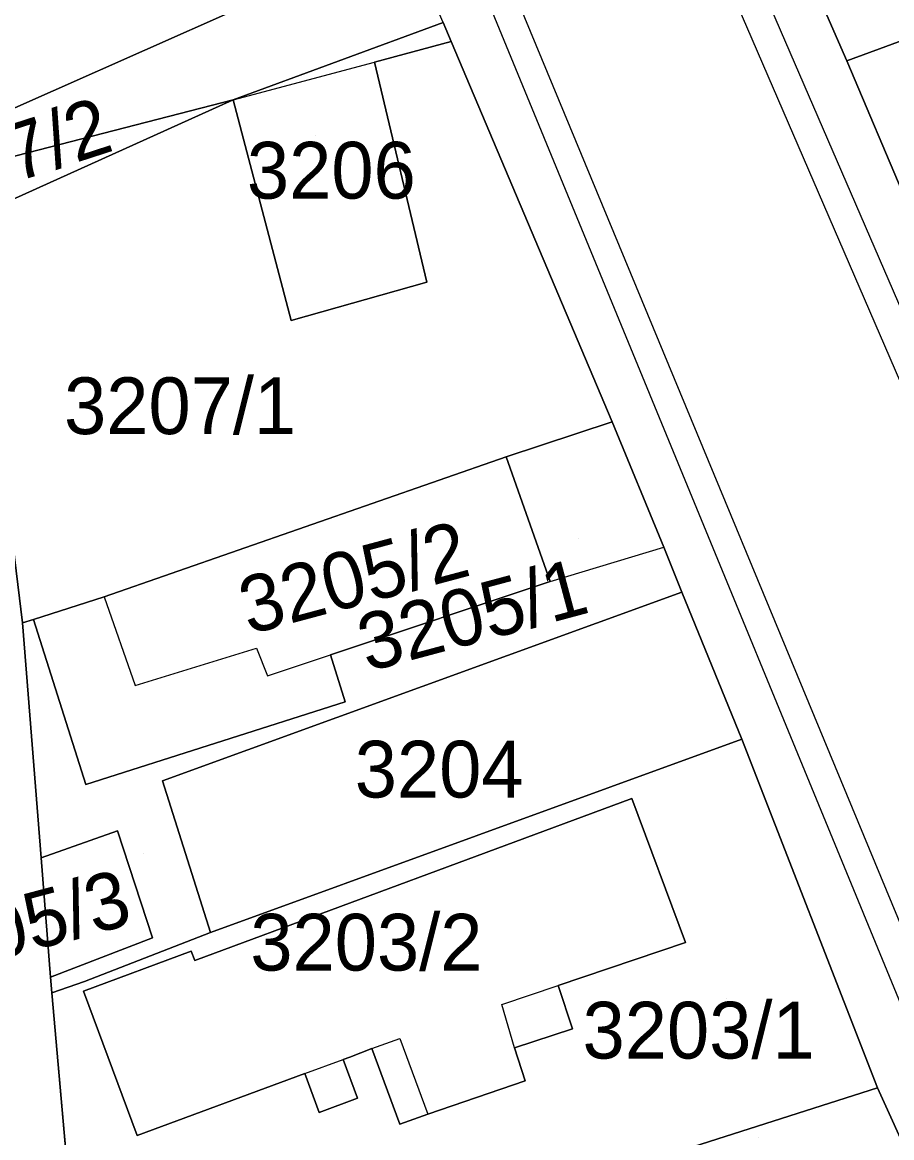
# Model space of a CAD drawing. Extents: x -262657 to -261595, y -1238015 to -1237156.
# Drawn here: x -261921.51 to -261890.88, y -1237853.34 to -1237814.02 of the extents above; entities that cross this region are included whole.
import ezdxf

# ---------------------------------------------------------------- set-up
doc = ezdxf.new("R2010")
doc.units = 0
for name, color, linetype in [('body_kn', 7, 'Continuous'), ('kladpar_druhypozemkov', 7, 'Continuous'), ('kladpar_hranice', 7, 'Continuous'), ('kladpar_parcelnecisla', 7, 'Continuous'), ('kladpar_plochy', 7, 'Continuous'), ('zappar_hrandruhpozemk', 7, 'Continuous')]:
    doc.layers.add(name, color=color, linetype=linetype)

msp = doc.modelspace()

# ---------------------------------------------------------------- linework, layer by layer
at = {"layer": 'body_kn'}
for p, q in [((-261906.69, -1237814.03), (-261906.69, -1237814.03)), ((-261906.69, -1237814.03), (-261906.69, -1237814.03)), ((-261906.4, -1237814.7), (-261906.4, -1237814.7)), ((-261906.4, -1237814.7), (-261906.4, -1237814.7)), ((-261909.1, -1237815.43), (-261909.1, -1237815.43)), ((-261909.1, -1237815.43), (-261909.1, -1237815.43)), ((-261892.46, -1237815.38), (-261892.46, -1237815.38)), ((-261892.46, -1237815.38), (-261892.46, -1237815.38)), ((-261914.09, -1237816.76), (-261914.09, -1237816.76)), ((-261914.09, -1237816.76), (-261914.09, -1237816.76)), ((-261907.26, -1237823.18), (-261907.26, -1237823.18)), ((-261912.04, -1237824.53), (-261912.04, -1237824.53)), ((-261900.73, -1237828.11), (-261900.73, -1237828.11)), ((-261904.47, -1237829.34), (-261904.47, -1237829.34)), ((-261904.47, -1237829.34), (-261904.47, -1237829.34)), ((-261898.91, -1237832.53), (-261898.91, -1237832.53)), ((-261902.91, -1237833.74), (-261902.91, -1237833.74)), ((-261902.91, -1237833.74), (-261902.91, -1237833.74)), ((-261918.63, -1237834.28), (-261918.63, -1237834.28)), ((-261918.63, -1237834.28), (-261918.63, -1237834.28)), ((-261898.28, -1237834.11), (-261898.28, -1237834.11)), ((-261898.28, -1237834.11), (-261898.28, -1237834.11)), ((-261921.12, -1237835.07), (-261921.12, -1237835.07)), ((-261921.12, -1237835.07), (-261921.12, -1237835.07)), ((-261921.51, -1237835.19), (-261921.51, -1237835.19)), ((-261913.26, -1237836.08), (-261913.26, -1237836.08)), ((-261910.65, -1237836.32), (-261910.65, -1237836.32)), ((-261912.88, -1237837.06), (-261912.88, -1237837.06)), ((-261917.54, -1237837.4), (-261917.54, -1237837.4)), ((-261910.14, -1237837.98), (-261910.14, -1237837.98)), ((-261896.16, -1237839.29), (-261896.16, -1237839.29)), ((-261919.28, -1237840.89), (-261919.28, -1237840.89)), ((-261916.58, -1237840.76), (-261916.58, -1237840.76)), ((-261900.04, -1237841.39), (-261900.04, -1237841.39)), ((-261918.16, -1237842.52), (-261918.16, -1237842.52)), ((-261920.85, -1237843.48), (-261920.85, -1237843.48)), ((-261920.85, -1237843.48), (-261920.85, -1237843.48)), ((-261914.88, -1237846.11), (-261914.88, -1237846.11)), ((-261916.93, -1237846.3), (-261916.93, -1237846.3)), ((-261898.14, -1237846.46), (-261898.14, -1237846.46)), ((-261915.56, -1237846.76), (-261915.56, -1237846.76)), ((-261915.44, -1237847.09), (-261915.44, -1237847.09)), ((-261920.52, -1237847.68), (-261920.52, -1237847.68)), ((-261919.32, -1237847.83), (-261919.32, -1237847.83)), ((-261902.63, -1237847.97), (-261902.63, -1237847.97)), ((-261920.48, -1237848.23), (-261920.48, -1237848.23)), ((-261920.48, -1237848.23), (-261920.48, -1237848.23)), ((-261919.36, -1237848.17), (-261919.36, -1237848.17)), ((-261919.36, -1237848.17), (-261919.36, -1237848.17)), ((-261904.62, -1237848.64), (-261904.62, -1237848.64)), ((-261902.13, -1237849.5), (-261902.13, -1237849.5)), ((-261908.21, -1237849.84), (-261908.21, -1237849.84)), ((-261909.2, -1237850.2), (-261909.2, -1237850.2)), ((-261909.2, -1237850.2), (-261909.2, -1237850.2)), ((-261904.17, -1237850.17), (-261904.17, -1237850.17)), ((-261904.17, -1237850.17), (-261904.17, -1237850.17)), ((-261910.21, -1237850.58), (-261910.21, -1237850.58)), ((-261909.97, -1237850.5), (-261909.97, -1237850.5)), ((-261911.56, -1237851.08), (-261911.56, -1237851.08)), ((-261911.56, -1237851.08), (-261911.56, -1237851.08)), ((-261903.79, -1237851.33), (-261903.79, -1237851.33)), ((-261891.38, -1237851.58), (-261891.38, -1237851.58)), ((-261891.38, -1237851.58), (-261891.38, -1237851.58)), ((-261909.7, -1237851.95), (-261909.7, -1237851.95)), ((-261911.05, -1237852.45), (-261911.05, -1237852.45)), ((-261907.22, -1237852.51), (-261907.22, -1237852.51)), ((-261908.21, -1237852.86), (-261908.21, -1237852.86)), ((-261917.47, -1237853.26), (-261917.47, -1237853.26)), ((-261895.57, -1237853.34), (-261895.57, -1237853.34))]:
    msp.add_line(p, q, dxfattribs=at)
at = {"layer": 'kladpar_druhypozemkov'}
for p, q in [((-261918.2, -1237818.16), (-261918.2, -1237818.16)), ((-261911.17, -1237818.03), (-261911.17, -1237818.03)), ((-261915.41, -1237826.93), (-261915.41, -1237826.93)), ((-261901.91, -1237832.22), (-261901.91, -1237832.22)), ((-261910.79, -1237832.7), (-261910.79, -1237832.7)), ((-261906.47, -1237839.89), (-261906.47, -1237839.89)), ((-261917.23, -1237843.33), (-261917.23, -1237843.33)), ((-261919.17, -1237844.63), (-261919.17, -1237844.63)), ((-261907.88, -1237845.63), (-261907.88, -1237845.63)), ((-261896.71, -1237848.43), (-261896.71, -1237848.43))]:
    msp.add_line(p, q, dxfattribs=at)
at = {"layer": 'kladpar_hranice'}
for points in [[(-261914.09, -1237816.76), (-261923.62, -1237819.21), (-261923.89, -1237818.34), (-261924, -1237817.96), (-261923.67, -1237817.87), (-261913.97, -1237813.57), (-261908.88, -1237811.31), (-261912.8, -1237801.81), (-261914.12, -1237798.61), (-261922.63, -1237778.24), (-261926.09, -1237769.65), (-261929.76, -1237759.16), (-261940.37, -1237728.85), (-261943.02, -1237721.29), (-261943.45, -1237719.94), (-261944.94, -1237715.14), (-261945.5, -1237713.33), (-261947.79, -1237697.89), (-261949.17, -1237690.86), (-261949.54, -1237688.95), (-261951.01, -1237681.71), (-261952.29, -1237673.66)], [(-261892.46, -1237815.38), (-261897.39, -1237804.1), (-261895.22, -1237803.36), (-261886.03, -1237800.22), (-261882.66, -1237799.08), (-261875.2, -1237796.53), (-261874.46, -1237799.37), (-261878.83, -1237801.48), (-261876.32, -1237809.44), (-261892.46, -1237815.38)], [(-261924.11, -1237817.62), (-261925.24, -1237804.88), (-261912.8, -1237801.81), (-261908.88, -1237811.31), (-261913.97, -1237813.57), (-261923.67, -1237817.87), (-261924, -1237817.96), (-261924.11, -1237817.62)], [(-261897.39, -1237804.1), (-261892.46, -1237815.38), (-261890.38, -1237820.3), (-261888.53, -1237824.53), (-261885.29, -1237831.79), (-261884.38, -1237833.72), (-261884, -1237834.66), (-261881.91, -1237839.28), (-261881.21, -1237840.86), (-261879.01, -1237845.76), (-261874.52, -1237855.64), (-261873.52, -1237857.83), (-261867.67, -1237871.68), (-261864.24, -1237879.6), (-261863.85, -1237880.67), (-261862.42, -1237883.92), (-261860.37, -1237888.77), (-261858.89, -1237892.19), (-261858.36, -1237893.51), (-261854.78, -1237901.75)], [(-261890.38, -1237820.3), (-261892.46, -1237815.38), (-261876.32, -1237809.44), (-261874, -1237808.64), (-261873.82, -1237809.05), (-261875.21, -1237809.56), (-261873.73, -1237813.58), (-261875.04, -1237813.91), (-261878.43, -1237816.1), (-261890.38, -1237820.3)], [(-261909.1, -1237815.43), (-261907.26, -1237823.18), (-261912.04, -1237824.53), (-261914.09, -1237816.76), (-261906.69, -1237814.03), (-261906.4, -1237814.7), (-261909.1, -1237815.43)], [(-261867.89, -1237908.17), (-261869.84, -1237903.85), (-261871.28, -1237900.38), (-261871.81, -1237899.1), (-261875.73, -1237889.62), (-261876.97, -1237886.62), (-261878.89, -1237882.22), (-261879.83, -1237879.78), (-261882.36, -1237872.9), (-261884.52, -1237867.46), (-261886.78, -1237861.7), (-261887.83, -1237859.39), (-261891.38, -1237851.58), (-261896.16, -1237839.29), (-261898.28, -1237834.11), (-261898.91, -1237832.53), (-261900.73, -1237828.11), (-261906.4, -1237814.7), (-261906.69, -1237814.03), (-261914.09, -1237816.76)], [(-261906.4, -1237814.7), (-261900.73, -1237828.11), (-261904.47, -1237829.34), (-261918.63, -1237834.28), (-261921.12, -1237835.07), (-261921.51, -1237835.19), (-261922.58, -1237826.51), (-261922.91, -1237823.77), (-261923.32, -1237821.16), (-261923.35, -1237820.94), (-261914.09, -1237816.76), (-261912.04, -1237824.53), (-261907.26, -1237823.18), (-261909.1, -1237815.43), (-261906.4, -1237814.7)], [(-261923.35, -1237820.94), (-261923.36, -1237820.86), (-261923.62, -1237819.21), (-261914.09, -1237816.76), (-261923.35, -1237820.94)], [(-261922.58, -1237826.51), (-261921.51, -1237835.19), (-261920.85, -1237843.48), (-261920.52, -1237847.68), (-261920.48, -1237848.23), (-261919.39, -1237860.46), (-261943.52, -1237862.78), (-261943.56, -1237862.36), (-261945.19, -1237844.04)], [(-261904.47, -1237829.34), (-261900.73, -1237828.11), (-261898.91, -1237832.53), (-261898.28, -1237834.11), (-261916.58, -1237840.76), (-261914.88, -1237846.11), (-261919.32, -1237847.83), (-261920.48, -1237848.23), (-261920.52, -1237847.68), (-261916.93, -1237846.3), (-261918.16, -1237842.52), (-261920.85, -1237843.48), (-261921.51, -1237835.19), (-261921.12, -1237835.07), (-261919.28, -1237840.89), (-261910.14, -1237837.98), (-261910.65, -1237836.32), (-261902.91, -1237833.74), (-261904.47, -1237829.34)], [(-261921.12, -1237835.07), (-261918.63, -1237834.28), (-261904.47, -1237829.34), (-261902.91, -1237833.74), (-261910.65, -1237836.32), (-261910.14, -1237837.98), (-261919.28, -1237840.89), (-261921.12, -1237835.07)], [(-261898.28, -1237834.11), (-261896.16, -1237839.29), (-261914.88, -1237846.11), (-261916.58, -1237840.76), (-261898.28, -1237834.11)], [(-261920.48, -1237848.23), (-261919.32, -1237847.83), (-261914.88, -1237846.11), (-261896.16, -1237839.29)], [(-261896.16, -1237839.29), (-261891.38, -1237851.58), (-261909.18, -1237857.27)], [(-261900.04, -1237841.39), (-261915.44, -1237847.09), (-261915.56, -1237846.76), (-261919.36, -1237848.17), (-261917.47, -1237853.26), (-261911.56, -1237851.08), (-261911.05, -1237852.45), (-261909.7, -1237851.95), (-261910.21, -1237850.58), (-261909.97, -1237850.5), (-261909.2, -1237850.2), (-261908.21, -1237852.86), (-261907.22, -1237852.51), (-261903.79, -1237851.33), (-261904.17, -1237850.17), (-261902.13, -1237849.5), (-261902.63, -1237847.97), (-261898.14, -1237846.46), (-261900.04, -1237841.39)], [(-261919.36, -1237848.17), (-261915.56, -1237846.76), (-261915.44, -1237847.09), (-261900.04, -1237841.39), (-261898.14, -1237846.46), (-261902.63, -1237847.97), (-261902.13, -1237849.5), (-261904.17, -1237850.17), (-261903.79, -1237851.33), (-261907.22, -1237852.51), (-261908.21, -1237852.86), (-261909.2, -1237850.2), (-261909.97, -1237850.5), (-261910.21, -1237850.58), (-261909.7, -1237851.95), (-261911.05, -1237852.45), (-261911.56, -1237851.08), (-261917.47, -1237853.26), (-261919.36, -1237848.17)], [(-261920.85, -1237843.48), (-261918.16, -1237842.52), (-261916.93, -1237846.3), (-261920.52, -1237847.68), (-261920.85, -1237843.48)], [(-261909.18, -1237857.27), (-261919.39, -1237860.46), (-261920.48, -1237848.23)], [(-261891.38, -1237851.58), (-261887.83, -1237859.39), (-261886.78, -1237861.7), (-261892.76, -1237864.26), (-261904.35, -1237869.07), (-261909.18, -1237857.27), (-261891.38, -1237851.58)]]:
    msp.add_lwpolyline(points, dxfattribs=at)
at = {"layer": 'kladpar_plochy'}
for p, q in [((-261914.88, -1237846.11), (-261896.16, -1237839.29)), ((-261896.16, -1237839.29), (-261891.38, -1237851.58)), ((-261900.04, -1237841.39), (-261915.44, -1237847.09)), ((-261898.14, -1237846.46), (-261900.04, -1237841.39)), ((-261919.32, -1237847.83), (-261914.88, -1237846.11)), ((-261902.63, -1237847.97), (-261898.14, -1237846.46)), ((-261915.56, -1237846.76), (-261919.36, -1237848.17)), ((-261915.44, -1237847.09), (-261915.56, -1237846.76)), ((-261920.48, -1237848.23), (-261919.32, -1237847.83)), ((-261902.13, -1237849.5), (-261902.63, -1237847.97)), ((-261919.39, -1237860.46), (-261920.48, -1237848.23)), ((-261919.36, -1237848.17), (-261917.47, -1237853.26)), ((-261904.17, -1237850.17), (-261902.13, -1237849.5)), ((-261909.97, -1237850.5), (-261909.2, -1237850.2)), ((-261909.2, -1237850.2), (-261908.21, -1237852.86)), ((-261903.79, -1237851.33), (-261904.17, -1237850.17)), ((-261910.21, -1237850.58), (-261909.97, -1237850.5)), ((-261909.7, -1237851.95), (-261910.21, -1237850.58)), ((-261917.47, -1237853.26), (-261911.56, -1237851.08)), ((-261911.56, -1237851.08), (-261911.05, -1237852.45)), ((-261891.38, -1237851.58), (-261909.18, -1237857.27)), ((-261907.22, -1237852.51), (-261903.79, -1237851.33)), ((-261911.05, -1237852.45), (-261909.7, -1237851.95)), ((-261908.21, -1237852.86), (-261907.22, -1237852.51))]:
    msp.add_line(p, q, dxfattribs=at)
for points in [[(-261892.46, -1237815.38), (-261897.39, -1237804.1), (-261895.22, -1237803.36), (-261886.03, -1237800.22), (-261882.66, -1237799.08), (-261875.2, -1237796.53), (-261874.46, -1237799.37), (-261878.83, -1237801.48), (-261876.32, -1237809.44)], [(-261924.11, -1237817.62), (-261925.24, -1237804.88), (-261912.8, -1237801.81), (-261908.88, -1237811.31), (-261913.97, -1237813.57), (-261923.67, -1237817.87), (-261924, -1237817.96)], [(-261890.38, -1237820.3), (-261892.46, -1237815.38), (-261876.32, -1237809.44), (-261874, -1237808.64), (-261873.82, -1237809.05), (-261875.21, -1237809.56), (-261873.73, -1237813.58), (-261875.04, -1237813.91), (-261878.43, -1237816.1)], [(-261909.1, -1237815.43), (-261907.26, -1237823.18), (-261912.04, -1237824.53), (-261914.09, -1237816.76), (-261906.69, -1237814.03), (-261906.4, -1237814.7)], [(-261906.4, -1237814.7), (-261900.73, -1237828.11), (-261904.47, -1237829.34), (-261918.63, -1237834.28), (-261921.12, -1237835.07), (-261921.51, -1237835.19), (-261922.58, -1237826.51), (-261922.91, -1237823.77), (-261923.32, -1237821.16), (-261923.35, -1237820.94), (-261914.09, -1237816.76), (-261912.04, -1237824.53), (-261907.26, -1237823.18), (-261909.1, -1237815.43)], [(-261923.35, -1237820.94), (-261923.36, -1237820.86), (-261923.62, -1237819.21), (-261914.09, -1237816.76)], [(-261945.19, -1237844.04), (-261926.38, -1237842.67), (-261926.52, -1237835.51), (-261930.89, -1237835.7), (-261931.15, -1237832.29), (-261942.76, -1237833.21), (-261946.3, -1237833.58), (-261946.74, -1237828.94), (-261922.58, -1237826.51), (-261921.51, -1237835.19), (-261920.85, -1237843.48), (-261920.52, -1237847.68), (-261920.48, -1237848.23), (-261919.39, -1237860.46), (-261943.52, -1237862.78), (-261943.56, -1237862.36)], [(-261904.47, -1237829.34), (-261900.73, -1237828.11), (-261898.91, -1237832.53), (-261898.28, -1237834.11), (-261916.58, -1237840.76), (-261914.88, -1237846.11), (-261919.32, -1237847.83), (-261920.48, -1237848.23), (-261920.52, -1237847.68), (-261916.93, -1237846.3), (-261918.16, -1237842.52), (-261920.85, -1237843.48), (-261921.51, -1237835.19), (-261921.12, -1237835.07), (-261919.28, -1237840.89), (-261910.14, -1237837.98), (-261910.65, -1237836.32), (-261902.91, -1237833.74)], [(-261921.12, -1237835.07), (-261918.63, -1237834.28), (-261904.47, -1237829.34), (-261902.91, -1237833.74), (-261910.65, -1237836.32), (-261910.14, -1237837.98), (-261919.28, -1237840.89)], [(-261898.28, -1237834.11), (-261896.16, -1237839.29), (-261914.88, -1237846.11), (-261916.58, -1237840.76)], [(-261919.36, -1237848.17), (-261915.56, -1237846.76), (-261915.44, -1237847.09), (-261900.04, -1237841.39), (-261898.14, -1237846.46), (-261902.63, -1237847.97), (-261902.13, -1237849.5), (-261904.17, -1237850.17), (-261903.79, -1237851.33), (-261907.22, -1237852.51), (-261908.21, -1237852.86), (-261909.2, -1237850.2), (-261909.97, -1237850.5), (-261910.21, -1237850.58), (-261909.7, -1237851.95), (-261911.05, -1237852.45), (-261911.56, -1237851.08), (-261917.47, -1237853.26)], [(-261920.85, -1237843.48), (-261918.16, -1237842.52), (-261916.93, -1237846.3), (-261920.52, -1237847.68)], [(-261891.38, -1237851.58), (-261887.83, -1237859.39), (-261886.78, -1237861.7), (-261892.76, -1237864.26), (-261904.35, -1237869.07), (-261909.18, -1237857.27)]]:
    msp.add_lwpolyline(points, close=True, dxfattribs=at)
for points in [[(-261897.39, -1237804.1), (-261892.46, -1237815.38), (-261890.38, -1237820.3), (-261888.53, -1237824.53), (-261885.29, -1237831.79), (-261884.38, -1237833.72), (-261884, -1237834.66), (-261881.91, -1237839.28), (-261881.21, -1237840.86), (-261879.01, -1237845.76), (-261874.52, -1237855.64), (-261873.52, -1237857.83), (-261867.67, -1237871.68), (-261864.24, -1237879.6), (-261863.85, -1237880.67), (-261862.42, -1237883.92), (-261860.37, -1237888.77), (-261858.89, -1237892.19), (-261858.36, -1237893.51), (-261854.78, -1237901.75)], [(-261871.81, -1237899.1), (-261875.73, -1237889.62), (-261876.97, -1237886.62), (-261878.89, -1237882.22), (-261879.83, -1237879.78), (-261882.36, -1237872.9), (-261884.52, -1237867.46), (-261886.78, -1237861.7), (-261887.83, -1237859.39), (-261891.38, -1237851.58), (-261896.16, -1237839.29), (-261898.28, -1237834.11), (-261898.91, -1237832.53), (-261900.73, -1237828.11), (-261906.4, -1237814.7), (-261906.69, -1237814.03), (-261914.09, -1237816.76), (-261923.62, -1237819.21), (-261923.89, -1237818.34), (-261924, -1237817.96), (-261923.67, -1237817.87), (-261913.97, -1237813.57)]]:
    msp.add_lwpolyline(points, dxfattribs=at)
at = {"layer": 'zappar_hrandruhpozemk'}
for p, q in [((-261924.51, -1237745.6), (-261870.74, -1237869.97)), ((-261906.69, -1237814.03), (-261912.03, -1237801.62)), ((-261914.09, -1237816.76), (-261909.1, -1237815.43)), ((-261902.91, -1237833.74), (-261898.91, -1237832.53)), ((-261918.63, -1237834.28), (-261917.54, -1237837.4)), ((-261917.54, -1237837.4), (-261913.26, -1237836.08)), ((-261904.62, -1237848.64), (-261902.63, -1237847.97)), ((-261904.17, -1237850.17), (-261904.62, -1237848.64)), ((-261909.2, -1237850.2), (-261908.21, -1237849.84)), ((-261908.21, -1237849.84), (-261907.22, -1237852.51)), ((-261911.56, -1237851.08), (-261910.21, -1237850.58))]:
    msp.add_line(p, q, dxfattribs=at)
for points in [[(-261857.29, -1237903.53), (-261871.7, -1237870.32), (-261925.44, -1237746.09), (-261934.35, -1237714.96)], [(-261875, -1237886.44), (-261927.55, -1237758.77), (-261932.46, -1237746.83)], [(-261917.3, -1237781.31), (-261875.05, -1237883.26), (-261864.96, -1237906.9)], [(-261913.26, -1237836.08), (-261912.88, -1237837.06), (-261910.65, -1237836.32)]]:
    msp.add_lwpolyline(points, dxfattribs=at)

# ---------------------------------------------------------------- texts
at = {"layer": 'kladpar_parcelnecisla'}
for s, rotation, p in [('3207/2', 18, (-261926.001, -1237821.05)), ('3205/2', 15, (-261913.536, -1237835.615)), ('3205/1', 15, (-261909.357, -1237836.927)), ('3205/3', 15, (-261925.461, -1237847.899))]:
    msp.add_text(s, height=2, rotation=rotation, dxfattribs=at).set_placement(p)
for s, p in [('3206', (-261913.6, -1237820.24)), ('3207/1', (-261920.044, -1237828.54)), ('3204', (-261909.8, -1237841.35)), ('3203/2', (-261913.48, -1237847.45)), ('3203/1', (-261901.773, -1237850.55))]:
    msp.add_text(s, height=2, dxfattribs=at).set_placement(p)

doc.saveas('drawing.dxf')
